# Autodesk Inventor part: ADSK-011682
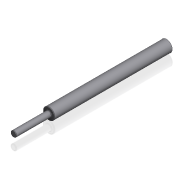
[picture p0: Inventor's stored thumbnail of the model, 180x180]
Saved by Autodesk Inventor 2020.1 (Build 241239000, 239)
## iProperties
Created: 2000-02
Part Number: ADSK-011682
Material: Pearson HRS
Document SubType Name: Modeling
Designer: cmcgourin
Density: 7.83 g/cm^3
Appearance: Métal - Acier
Mass: 1036.86 g
Surface Area: 245.496 cm^2
Volume: 132.422 cm^3
Control State: 0
Checked Out: False
Master: False
Shininess: 0.0
Length Units: 11269
Angle Units: 11279
Time Units: 11290
Mass Units: 11283
Length Display Precision: 3
Angle Display Precision: 2
Compacted: True
Cutlength: 23.25
Material Desc: Material Description goes here
Material_Number: Pearson
Dimensions: 25x330x25 mm
Mass: 1,037 kg
DocNumber: ADSK-011682.ipt
Folder: 01 - Themengebiete\Simplification\01 - Packaging machine\
VDS_Category: 3D Komponenten
VLT_Material: Pearson HRS
Density: 0.0
Volumn: 0.0
Area: 0.0
PropertySet Name: Model Information
Author: cmcgourin
Revision Number: -
Title: shaft
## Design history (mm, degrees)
node "Chamfer1" dims "d6" = 1, "d7" = 1, "d18" = 45 deg
node "Hole1" dims "d12" = 8.376, "d13" = 9.525, "d14" = 6.35, "d15" = 60 deg, "d16" = 27.3, "d17" = 118 deg, "d21" = 20
node "Solide1"
  node "Extrusion1" dims "d1" = 254, "d2" = 0
  node "Extrusion2" dims "d4" = 76, "d5" = 0
sketch "Sketch1"
  geometry: C1 r 12.5 at (0, 0); 1 further point
  constraints: 1 centre point, 1 coincident
  dimensions: "d0" = 25 diameter of C1
sketch "Sketch2"
  geometry: C1 r 12.5 at (0, 0) reference; C2 r 6.25 at (0, 0)
  constraints: 1 centre point, 1 coincident
  dimensions: "d3" = 12.5 diameter of C2
node "Corps solides"
node "Corps surfaciques"
sketch "Sketch3"
  geometry: C1 r 12.5 at (0, 0) reference; 1 further point
  constraints: 1 coincident
